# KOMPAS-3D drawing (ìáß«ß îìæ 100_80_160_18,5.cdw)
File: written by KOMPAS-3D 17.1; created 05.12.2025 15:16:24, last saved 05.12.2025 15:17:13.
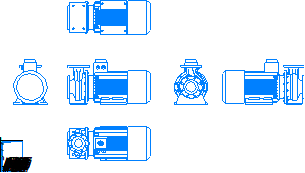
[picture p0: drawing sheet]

Sheet 1: A4, portrait

Title block, sheet 1: name: Насос МНС / 100_80_160_18,5; material: Сталь 10  ГОСТ 1050-88; mass: 309,93; sheets: 1; sheet format: A4

Views: Вид 1, Спереди, Проекционный вид 2, Проекционный вид 3, Проекционный вид 4, Проекционный вид 5, Проекционный вид 6
Referenced files in \\adlc.lan\data\АДЛ_ПКД\3D-модели\ADL production\Насосы ГРАНПАМП\Насосы ГРАНПАМП серии МНС\KOMPAS 3D\: Насос МНС 100-80-160_18,5.m3d
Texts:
  Andrey
  АДЛ
Dimensions and other numbers on the sheet: 1:1; 1; 100_80_160_18,5; 309,93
